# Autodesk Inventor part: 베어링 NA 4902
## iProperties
IsCustomPart: 0
Manager: KYOUNG IL JANG
Company: 한국ATC센터
Created: 2009-02
Part Number: 베어링 NA 4902
Material: Steel, Mild
Description: 니들 롤러 베어링 - 경계 치수 및 공차
Document SubType Name: Modeling
Standard: KS B 2029
Standards Organization: KS
Language: ko-KR
Size Designation: NA 4902 - 15 x 28 x 13
Categories: <MemberInstance><Categories><Category DisplayName="샤프트 부품" InternalName="7f7aeb1f-a693-4053-b835-cee3144e0d98" Mnemonic="SHFT"><Category DisplayName="베어링" Inter
Density: 1 g/cm^3
Checked By: KYOUNG IL JANG
Vendor: CBT Solutions
Designer: KYOUNG IL JANG
Author: KYOUNG IL JANG
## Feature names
1. IDS_ARRAYROLLER[SIMPL:T] [Circular Pattern]
